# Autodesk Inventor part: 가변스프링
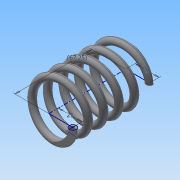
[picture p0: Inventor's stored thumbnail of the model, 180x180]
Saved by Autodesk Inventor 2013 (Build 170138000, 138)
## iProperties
Created: 2019-10
Part Number: 가변스프링
Material: 일반
Document SubType Name: Modeling
Designer: Administrator
Density: 1 g/cm^3
Mass: 18.3472 g
Surface Area: 124.146 cm^2
Volume: 18.3472 cm^3
Author: Administrator
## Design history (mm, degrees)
sketch "스케치1"
  geometry: L1 (0, 0)-(0, 67.25); L2 (0, 0)-(21, 0); L3 (0, 67.25)-(21, 67.25); C1 r 3 at (21, 0)
  constraints: 6 end point, 2 horizontal, 1 centre point, 1 coincident, 1 vertical
  dimensions: "d2" = 67.25 distance of L1.start L1.end (derived); "d3" = 21 distance of L1.start L2.end; "d4" = 6 diameter of C1; "d5" = 21 distance of L1.end L3.end
feature "코일1" pitch "d6" = 10; turns "d8" = 5; dims "d7" = 67.25 (= d2), "d9" = 0, angle "d10" = 90 deg, angle "d11" = 90 deg, "d12" = 0, "d13" = 0
sketch "스케치2"
  geometry: L1 (-37.447, 67.25)-(37.447, 67.25); L2 (37.447, 67.25)-(37.447, 0); L3 (37.447, 0)-(-37.447, 0); L4 (-37.447, 0)-(-37.447, 67.25); 2 further points
  constraints: 8 end point, 2 parallel, 1 coincident, 1 horizontal, 1 midpoint, 1 perpendicular
  dimensions: "d14" = 67.25 distance between parallel lines of L3 L1 (= d2)
extrude "돌출1" sketch "스케치2" stored distance "d17" = 0; taper "d18" = 0 deg
node "솔리드1"
